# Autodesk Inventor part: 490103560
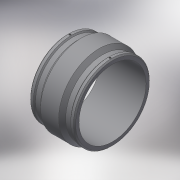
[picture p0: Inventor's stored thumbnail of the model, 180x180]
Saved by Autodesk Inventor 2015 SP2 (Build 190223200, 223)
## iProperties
Created: 2017-06
Part Number: 490103560
Material: Generic
Description: PLASSON COUPLER 560
Document SubType Name: Modeling
Designer: KIM
Mass: 30984.5 g
Surface Area: 16081.4 cm^2
Volume: 30984.5 cm^3
Density: 1 g/cm^3
Appearance: Default
Author: KIM
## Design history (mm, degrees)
derived "490103.ipt"
feature "Solid1::490103.ipt"
tag "TaggingFeature1"
body "Solid1"
other parameters: "d13" = 376, "d15" = 188, "d16" = 188, "d22" = 634, "d23" = 674, "d24" = 614.98, "d25" = 135 deg, "d26" = 150.4, "d27" = 135 deg, "d29" = 317, "d35" = 15, "d39" = 0, "d40" = 4, "d41" = 14, "d42" = 0, "d43" = 135 deg, "d44" = 41.36, "d46" = 6, "d47" = 0, "L_" = 376, "L_1" = 188, "D_" = 674, "A_" = 317, "d_2" = 12
